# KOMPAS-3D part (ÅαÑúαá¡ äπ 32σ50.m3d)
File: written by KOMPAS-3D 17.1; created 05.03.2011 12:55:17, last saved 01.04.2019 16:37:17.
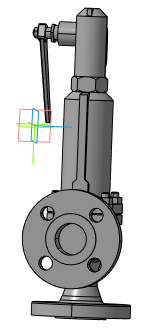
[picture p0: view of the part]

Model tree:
1. Плоскость XY
2. Плоскость ZX
3. Плоскость ZY
4. Ось X
5. Ось Y
6. Ось Z
7. Начало координат
8. Операция без истории:2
